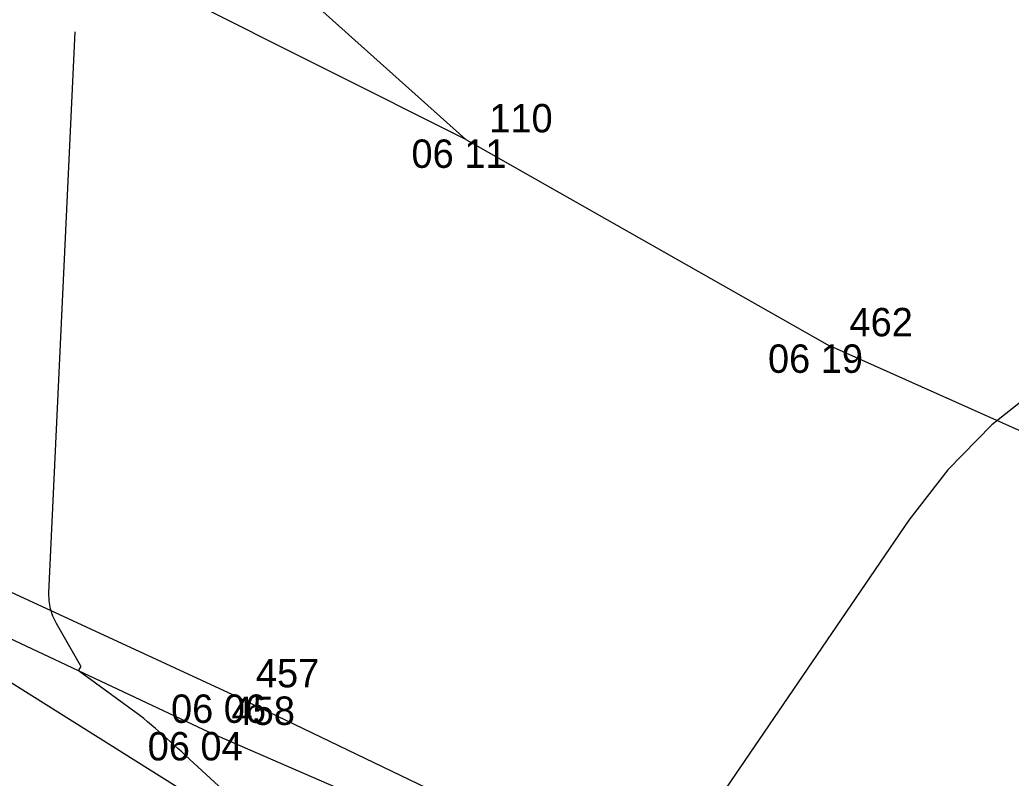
# Model space of a CAD drawing. Extents: x -711234 to -710007, y -1026313 to -1025448.
# Drawn here: x -711048.26 to -711038.49, y -1025891.84 to -1025884.37 of the extents above; entities that cross this region are included whole.
import ezdxf

# ---------------------------------------------------------------- set-up
doc = ezdxf.new("R2010")
doc.units = 0
for name, color, linetype in [('Ex_Major Contours', 7, 'Continuous'), ('Ex_Minor Contours', 7, 'Continuous'), ('Z_body', 7, 'Continuous'), ('Z_body_cisla', 7, 'Continuous'), ('Z_body_vysky_redukovane', 7, 'Continuous'), ('Z_katastr_hranice', 7, 'Continuous'), ('Z_komunikace', 7, 'Continuous'), ('Z_vdz12_plna', 7, 'Continuous'), ('Z_vdz25_plna', 7, 'Continuous')]:
    doc.layers.add(name, color=color, linetype=linetype)

# ---------------------------------------------------------------- blocks, each defined once
blk = doc.blocks.new('POINT_DISPLAY')
blk.add_line((0, 0), (0, 0))

msp = doc.modelspace()

# ---------------------------------------------------------------- linework, layer by layer
at = {"layer": 'Ex_Major Contours'}
msp.add_lwpolyline([(-711045.5229, -1025892.6339), (-711046.6246, -1025891.6205), (-711046.6613, -1025891.5868), (-711046.6982, -1025891.5533), (-711046.7351, -1025891.5199), (-711046.7722, -1025891.4866), (-711046.9209, -1025891.3538), (-711046.9584, -1025891.321), (-711046.9967, -1025891.2892), (-711047.0357, -1025891.2583), (-711047.0754, -1025891.2282), (-711047.6669, -1025890.7919), (-711047.6708, -1025890.7881), (-711047.6726, -1025890.7839), (-711047.6725, -1025890.7793), (-711047.6703, -1025890.7743), (-711047.6577, -1025890.7537), (-711047.6553, -1025890.7485), (-711047.6544, -1025890.7433), (-711047.6551, -1025890.7381), (-711047.6574, -1025890.7328), (-711047.8955, -1025890.3208), (-711047.9306, -1025890.2491), (-711047.9546, -1025890.1746), (-711047.9675, -1025890.0974), (-711047.9693, -1025890.0175), (-711047.7098, -1025884.4875)], dxfattribs=at)
at = {"layer": 'Ex_Minor Contours'}
msp.add_lwpolyline([(-711038.1911, -1025887.9789), (-711038.6765, -1025888.3635), (-711039.1111, -1025888.8047), (-711039.4951, -1025889.3023), (-711041.5402, -1025892.3017)], dxfattribs=at)
at = {"layer": 'Z_katastr_hranice'}
msp.add_lwpolyline([(-711143.66, -1025881.69), (-711119.52, -1025871.38), (-711081.1, -1025874.43), (-711069.6, -1025880.3), (-711060.15, -1025885.29), (-711049.51, -1025890.17), (-711031.09, -1025901.74), (-711010.7, -1025906.92), (-710992.71, -1025905.14), (-710973.48, -1025897.7)], dxfattribs=at)
at = {"layer": 'Z_komunikace'}
for p, q in [((-711056.04, -1025886.85), (-711046.39, -1025891.39)), ((-711046.39, -1025891.39), (-711043.17, -1025892.79))]:
    msp.add_line(p, q, dxfattribs=at)
at = {"layer": 'Z_vdz12_plna'}
for p, q in [((-711043.86, -1025885.55), (-711040.3, -1025887.57)), ((-711040.3, -1025887.57), (-711030.66, -1025891.88))]:
    msp.add_line(p, q, dxfattribs=at)
at = {"layer": 'Z_vdz25_plna'}
for p, q in [((-711046.99, -1025882.75), (-711043.86, -1025885.55)), ((-711043.86, -1025885.55), (-711047.67, -1025883.64)), ((-711055.85, -1025886.54), (-711046.16, -1025891.02)), ((-711046.16, -1025891.02), (-711043.02, -1025892.53))]:
    msp.add_line(p, q, dxfattribs=at)

# ---------------------------------------------------------------- block references
at = {"layer": 'Z_body'}
for p in [(-711043.86, -1025885.55), (-711040.3, -1025887.57), (-711046.16, -1025891.02), (-711046.39, -1025891.39)]:
    msp.add_blockref('POINT_DISPLAY', p, dxfattribs=at)

# ---------------------------------------------------------------- texts
at = {"layer": 'Z_body_cisla'}
for s, p in [('110', (-711043.63, -1025885.48)), ('462', (-711040.08, -1025887.49)), ('457', (-711045.93, -1025890.95)), ('458', (-711046.17, -1025891.32))]:
    msp.add_text(s, height=0.28, dxfattribs=at).set_placement(p)
at = {"layer": 'Z_body_vysky_redukovane'}
for s, p in [('06 11', (-711044.3967, -1025885.83)), ('06 19', (-711040.8833, -1025887.85)), ('06 06', (-711046.7667, -1025891.3)), ('06 04', (-711046.9967, -1025891.67))]:
    msp.add_text(s, height=0.28, dxfattribs=at).set_placement(p)

doc.saveas('drawing.dxf')
